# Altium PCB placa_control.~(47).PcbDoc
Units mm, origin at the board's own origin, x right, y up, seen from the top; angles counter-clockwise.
Board outline 58.75 x 106.25 mm, 2 copper layers (Top Layer, Bottom Layer); 36 components, 32 nets, 144 pads, 100 vias.
Unrouted connection lines stored in the file: 34.
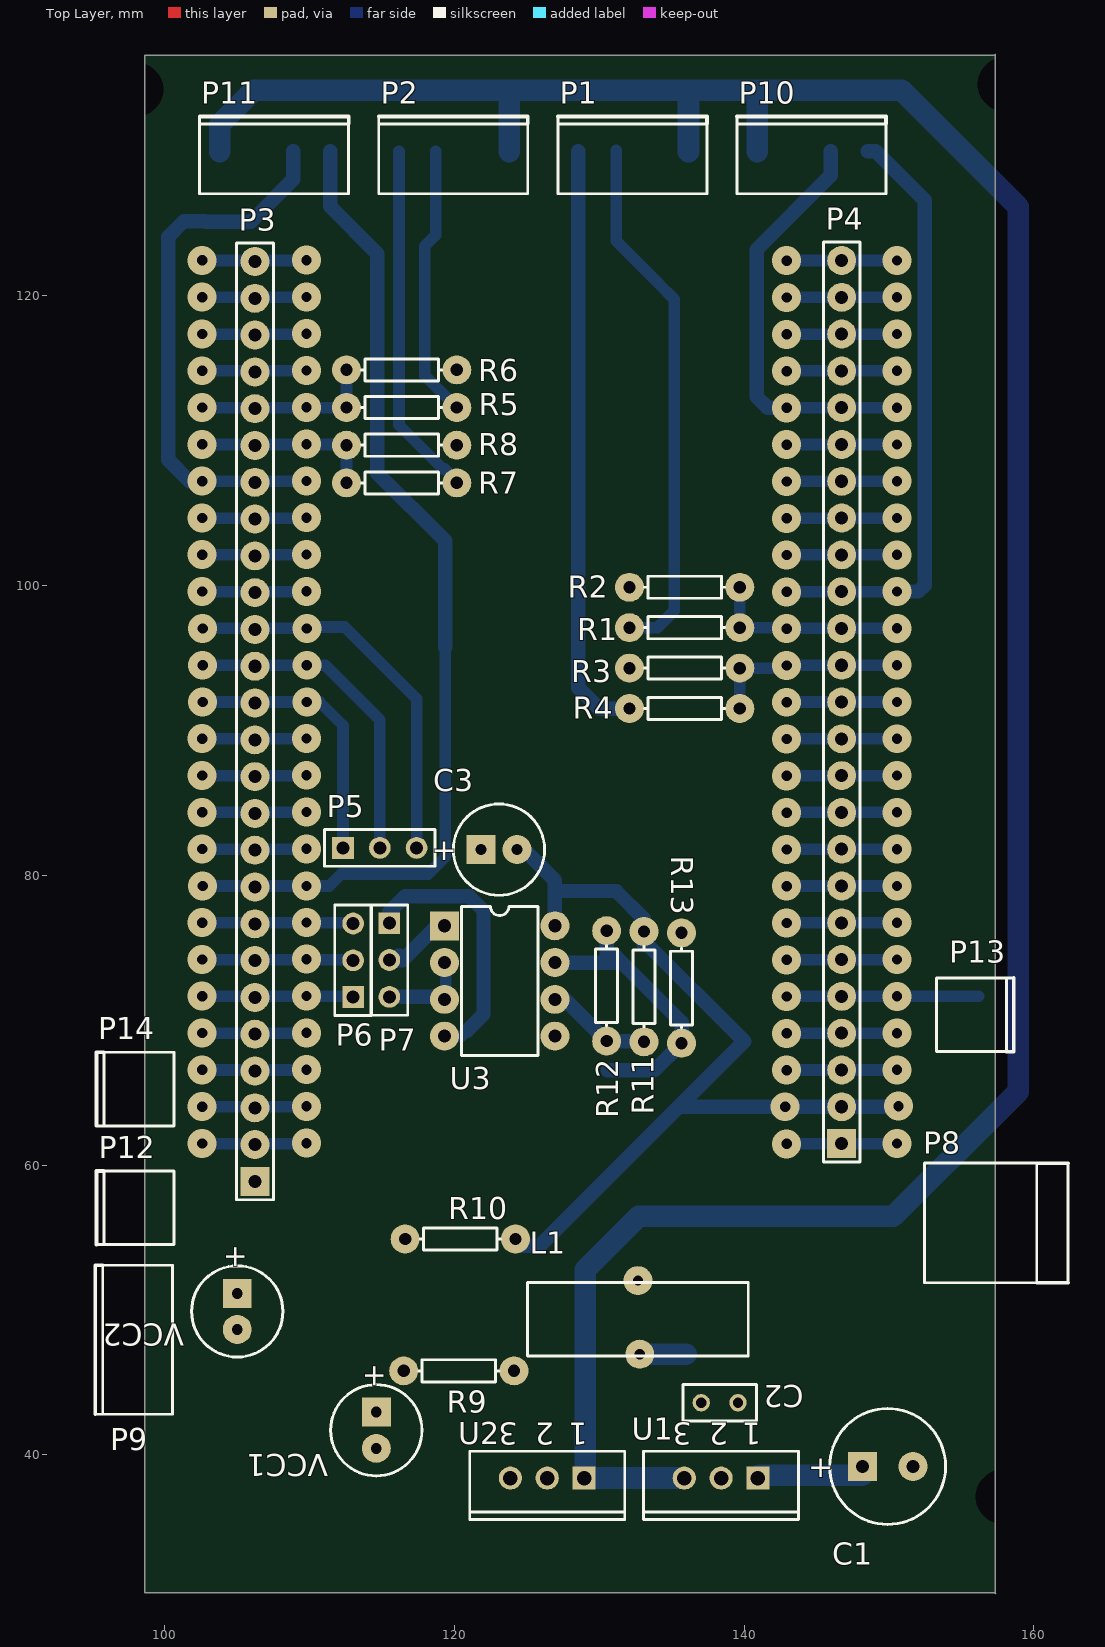
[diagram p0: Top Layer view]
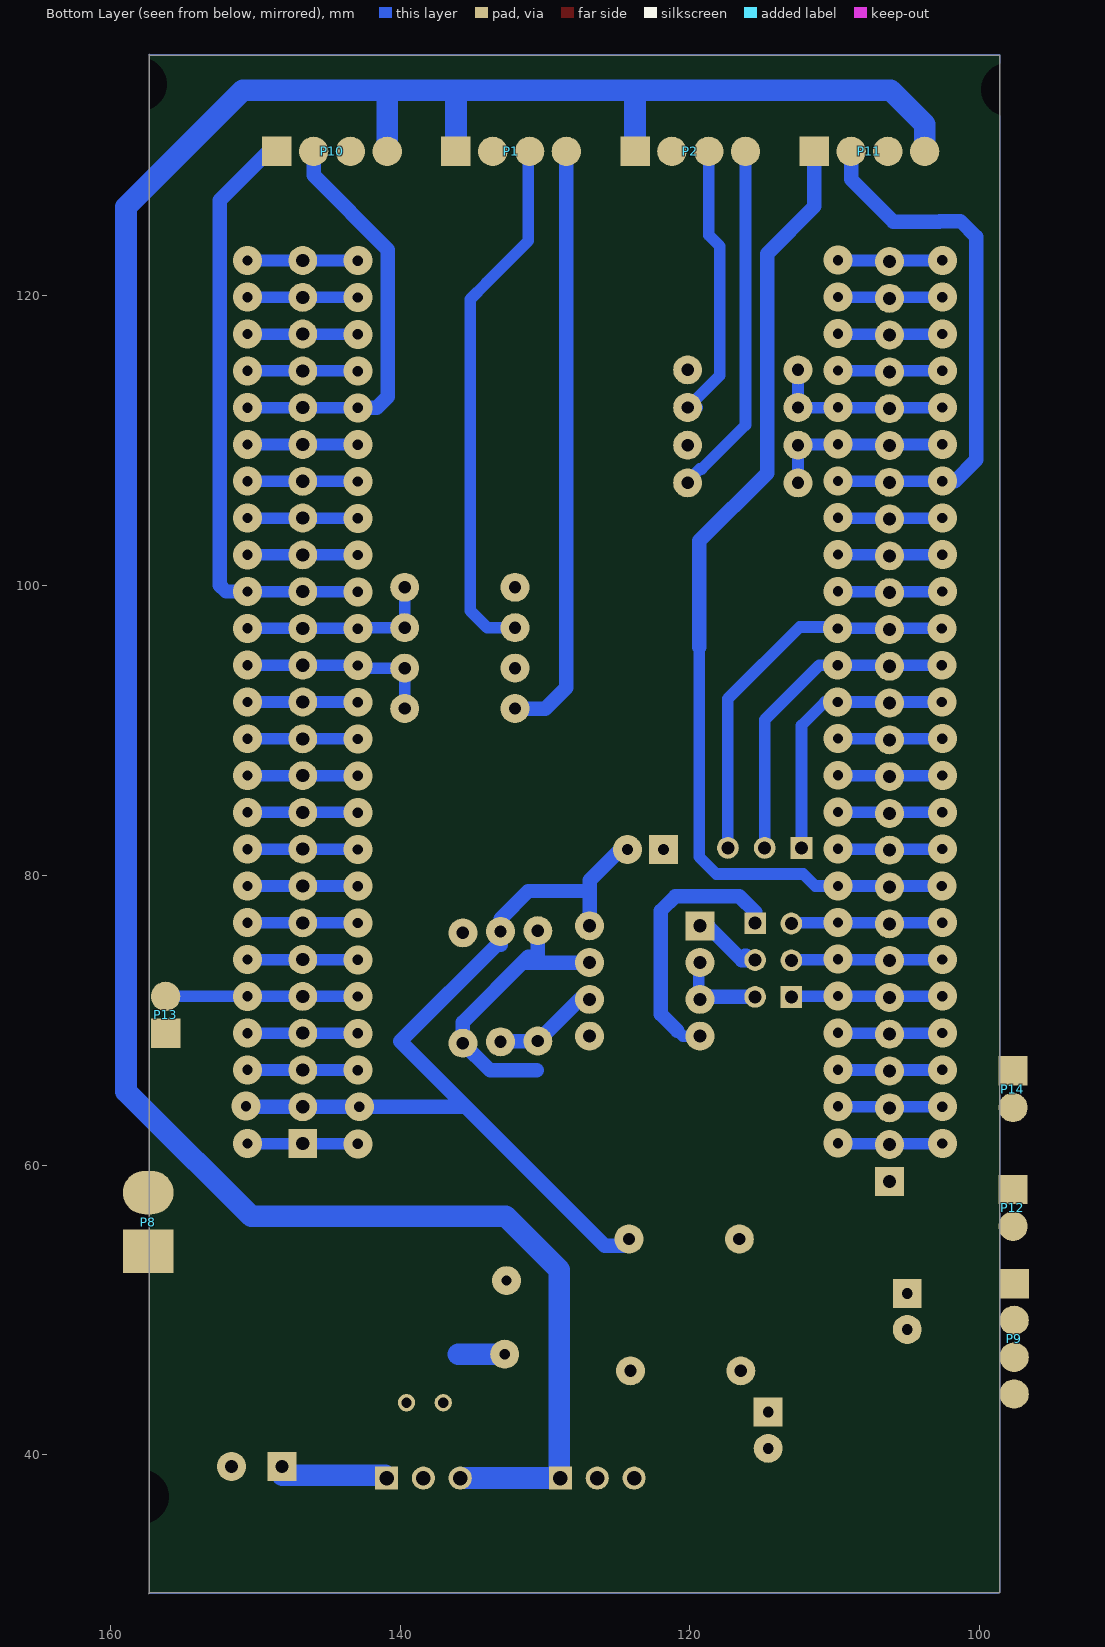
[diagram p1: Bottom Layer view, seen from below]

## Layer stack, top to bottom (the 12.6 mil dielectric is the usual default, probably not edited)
Top Layer: signal copper 0.0356
Dielectric: dielectric 0.32, FR-4, Dk 4.8
Bottom Layer: signal copper 0.0356

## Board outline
98.6,136.625 157.275,136.625 157.325,136.675 157.325,30.45 157.35,30.425 157.3,30.475 98.625,30.475 98.6,30.5

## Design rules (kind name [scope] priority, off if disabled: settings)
Clearance [All] p1: gap=0.4
ComponentClearance [All] p1: gap=0.254 collisioncheckmode=2 verticalgap=0.254
PlaneConnect [All] p1: planeconnectstyle=Direct reliefexpansion=0.508 reliefentries=4 reliefconductorwidth=0.6 reliefairgap=0.254
PolygonConnect [All] p1: connectstyle=Direct reliefconductorwidth=0.6 reliefentries=4 polygonreliefangle="90 Angle"
RoomDefinition REGULADOR [InComponentClass('REGULADOR')] p1: confinementstyle=ConfineIn formatcopy=TRUE lockcomponents=FALSE outline 99.475,34.9 155.025,34.9 155.025,58.375 99.475,58.375
RoomDefinition INTERFAZ [InComponentClass('INTERFAZ')] p2: confinementstyle=ConfineIn formatcopy=TRUE lockcomponents=FALSE outline 110.775,62.675 143.675,62.675 143.675,88.075 110.775,88.075
RoomDefinition ENCODER [InComponentClass('ENCODER')] p3: confinementstyle=ConfineOut formatcopy=TRUE lockcomponents=FALSE outline 141.4,147.25 141.4,152.45 116,152.45 116,147.25
RoomDefinition BOARD-ARM [InComponentClass('BOARD-ARM')] p4: confinementstyle=ConfineOut formatcopy=TRUE lockcomponents=FALSE outline 166.025,120.7 232.827,120.7 232.827,146.1 166.025,146.1
RoomDefinition placa_control_esquema [InComponentClass('placa_control_esquema')] p5: confinementstyle=ConfineIn formatcopy=TRUE lockcomponents=FALSE outline 93.3,34.925 163.875,34.925 163.875,136.6 93.3,136.6
RoutingVias [All] p1: holewidth=0.711 width=2 viastyle="Through Hole" minholewidth=0.711 minwidth=1.27 maxholewidth=0.711 maxwidth=2
SolderMaskExpansion [All] p1: expansion=0.102
TestPointUsage [All] p1: valid=0 allowmultiple=FALSE
Testpoint [All] p1: side=15 testpointundercomponent=TRUE minsize=1.016 maxsize=2.54 preferedsize=1.524 minholesize=0 maxholesize=1.016 preferedholesize=0.813 testpointgrid=0.025 style=1023 order=0-112345678
Width [All] p1: maxlimit=1.5 minlimit=0.8 preferedwidth=0.8
17 further rules are at their usual default settings.

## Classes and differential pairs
component class INTERFAZ: C3 P12 R11 R12 R13 U3
component class ENCODER: P1 P2 R1 R2 R3 R4 R5 R6 R7 R8
component class BOARD-ARM: P3 P4 P5 P6 P7 P13 P14
component class REGULADOR: C1 C2 L1 P8 R9 R10 U1 U2 VCC1 VCC2
component class placa_control_esquema: P9 P10 P11

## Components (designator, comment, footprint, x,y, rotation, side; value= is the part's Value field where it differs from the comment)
C1 "Cap Pol3" CAPPR3.5-8X15 149.9,39.2 r0 top
C2 "Cap" RAD-0.1 138.3,43.6 r0 top
C3 "Cap" CAPPR2.5-6.3X5 123.069,81.783 r0 top
L1 "Inductor Iron" bobina_Choque 135.2,51.9 r180 top
P1 "Header 4" HDR1X5 128.533,137.6 r180 top
P2 "Header 4" HDR1X5 116.167,137.6 r180 top
P3 "header26" HDR1x26 111.3,91.9 r90 top
P4 "Header 25" HDR1X25 146.73,61.49 r90 top
P5 "Header 3" HDR1X3 112.3,81.9 r0 top
P6 "Header 3" HDR1X3 113,71.6 r90 top
P7 "Header 3" HDR1X3 115.5,76.7 r270 top
P8 "Header 2" pwheader1x2 157.4,56.2 r90 top
P9 "Header 4" HDR1X5 90,44.2 r270 top
P10 "Header 4" HDR1X5 140.9,137.6 r180 top
P11 "Header 4" HDR1X5 103.8,137.6 r180 top
P12 "Header 2" wf2s 97.7,50.7 r270 top
P13 "Header 2" wf2s 156.2,76.725 r90 top
P14 "Header 2" wf2s 97.7,58.9 r270 top
R1 "metal film 2%" AXIAL-0.3 135.884,97.102 r180 top
R2 "metal film 2%" AXIAL-0.3 135.884,99.894 r0 top
R3 "metal film 2%" AXIAL-0.3 135.884,91.518 r180 top
R4 "metal film 2%" AXIAL-0.3 135.884,94.31 r0 top
R5 "metal film 2%" AXIAL-0.3 116.35,112.3 r0 top
R6 "metal film 2%" AXIAL-0.3 116.35,114.9 r180 top
R7 "metal film 2%" AXIAL-0.3 116.35,107.1 r0 top
R8 "metal film 2%" AXIAL-0.3 116.35,109.7 r180 top
R9 "Carbon 1/8w 5%" AXIAL-0.3 120.3,45.8 r0 top
R10 "Carbon 1/8w 5%" AXIAL-0.3 120.4,54.9 r0 top
R11 "Carbon 1/8w 5%" AXIAL-0.3 133.075,72.325 r90 top
R12 "Carbon 1/8w 5%" AXIAL-0.3 130.501,72.375 r270 top
R13 "Carbon 1/8w 5%" AXIAL-0.3 135.675,72.225 r270 top
U1 "LM78L12ACZ" T03B 138.4,38.4 r180 top
U2 "LM78L05ACZ" T03B 126.4,38.4 r180 top
U3 "SN75176BP" 626-05 123.119,72.715 r270 top
VCC1 "LED2" CAPPR2.5-6.3X5 114.6,41.7 r270 top
VCC2 "LED2" CAPPR2.5-6.3X5 105,49.9 r270 top

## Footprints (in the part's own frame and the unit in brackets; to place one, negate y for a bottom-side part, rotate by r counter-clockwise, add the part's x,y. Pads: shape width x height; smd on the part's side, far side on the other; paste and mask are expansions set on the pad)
626-05 [mm] "DIP; 8 Leads; Row Spacing 7.62 mm; Pitch 2.54 mm"
  rect 2x2 hole 0.9: 1(-3.81,-3.81)
  round 2 hole 0.9: 2(-1.27,-3.81) 3(1.27,-3.81) 4(3.81,-3.81) 5(3.81,3.81) 6(1.27,3.81) 7(-1.27,3.81) 8(-3.81,3.81)
  silkscreen extent -5.15,-2.65 5.15,2.65
AXIAL-0.3 [mm] "Resistor; 2 Leads"
  round 2 hole 0.85: 1(-3.81,0) 2(3.81,0)
  silkscreen extent -2.77,-0.76 2.77,0.76
bobina_Choque [mm]
  round 2 hole 0.7: 1(2.54,-0.127) 2(2.413,4.953)
  silkscreen extent -5.08,0 10.16,5.08
CAPPR2.5-6.3X5 [mm] "Capacitor, Electrolytic, Radial; Body 6.3 x 5 mm (Dia.xH typ); Pin Spacing 2.5 mm (typ)"
  rect 2x2 hole 0.75: 1(-1.25,0)
  round 2 hole 0.75: 2(1.25,0)
  silkscreen extent -3.15,-3.15 3.15,3.15
CAPPR3.5-8X15 [mm] "Capacitor, Electrolytic, Radial; Body 8 x 15 mm (Dia.xH typ); Pin Spacing 3.5 mm (typ)"
  rect 2x2 hole 0.9: 1(-1.75,0)
  round 2 hole 0.9: 2(1.75,0)
  silkscreen extent -4,-4 4,4
HDR1X3 [mm] "Connector; Header; 3 Position"
  rect 1.5x1.5 hole 0.9: 1(0,0)
  round 1.5 hole 0.9: 2(2.54,0) 3(5.08,0)
  silkscreen extent -1.27,-1.27 6.35,1.27
HDR1X5 [mil]
  rect 80x80 smd far side: 1(-300,300)
  round 80 smd far side: 2(-200,300) 3(-100,300) 4(0,300)
  silkscreen extent -350,205 55,415
HDR1X25 [mm] "Connector; Header; 25 Position"
  rect 2x2 hole 0.9: 1(0,0)
  round 2 hole 0.9: 2(2.54,0) 3(5.08,0) 4(7.62,0) 5(10.16,0) 6(12.7,0) 7(15.24,0) 8(17.78,0) 9(20.32,0) 10(22.86,0) 11(25.4,0) 12(27.94,0) 13(30.48,0) 14(33.02,0) 15(35.56,0) 16(38.1,0) 17(40.64,0) 18(43.18,0) 19(45.72,0) 20(48.26,0) 21(50.8,0) 22(53.34,0) 23(55.88,0) 24(58.42,0) 25(60.96,0)
  silkscreen extent -1.27,-1.27 62.23,1.27
HDR1x26 [mm]
  rect 2x2 hole 0.9: 1(-33.02,5.08)
  round 2 hole 0.9: 2(-30.48,5.08) 3(-27.94,5.08) 4(-25.4,5.08) 5(-22.86,5.08) 6(-20.32,5.08) 7(-17.78,5.08) 8(-15.24,5.08) 9(-12.7,5.08) 10(-10.16,5.08) 11(-7.62,5.08) 12(-5.08,5.08) 13(-2.54,5.08) 14(0,5.08) 15(2.54,5.08) 16(5.08,5.08) 17(7.62,5.08) 18(10.16,5.08) 19(12.7,5.08) 20(15.24,5.08) 21(17.78,5.08) 22(20.32,5.08) 23(22.86,5.08) 24(25.4,5.08) 25(27.94,5.08) 26(30.48,5.08)
  silkscreen extent -34.29,3.81 31.75,6.35
pwheader1x2 [mm]
  rect 3x3.5 smd far side: 1(-2.159,0)
  oval 3x3.5 smd far side: 2(1.905,0)
  silkscreen extent -4.32,-4.95 3.94,4.95
RAD-0.1 [mm] "Indicating Instrument; 2 Leads"
  round 1.2 hole 0.7: 1(-1.27,0) 2(1.27,0)
  silkscreen extent -2.54,-1.27 2.54,1.27
T03B [mm] "TO, Thru-Hole, Vertical, Heatsink Mounted; 3 In-Line Leads; Pitch 2.54 mm"
  rect 1.6x1.6 hole 1: 1(-2.54,0)
  round 1.6 hole 1: 2(0,0) 3(2.54,0)
  silkscreen extent -5.35,-1.85 5.35,2.85
wf2s [mil]
  rect 80x80 smd far side: 1(-300,0)
  round 80 smd far side: 2(-200,0)
  silkscreen extent -350,-95 -150,115

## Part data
C1: "Polarized Capacitor 35V"
C2 C3: "Capacitor"
L1: "Magnetic-Core Inductor"
P1 P2 P9 P10 P11: "Header, 4-Pin"
P3: library part Component_1
P4: "Header, 25-Pin"
P5 P6 P7: "Header, 3-Pin"
P8 P12 P13 P14: "Header, 2-Pin"
R1 R2 R3 R4 R5 R6 R7 R8 R9 R10 R11 R12 R13: library part "Res Semi", "Semiconductor Resistor"
U1 U2: "3-Terminal Positive Regulator"
U3: "Differential Bus Transceiver"
VCC1 VCC2: "Typical RED, GREEN, YELLOW, AMBER GaAs LED"

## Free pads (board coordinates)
  round 1.524 hole 3.75: 0(95.775,37.35) 0(98.025,134.25) 0(157.85,37.1) 0(157.975,134.625)

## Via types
v1: diameter 2, hole 0.711, Top Layer to Bottom Layer, 100 vias

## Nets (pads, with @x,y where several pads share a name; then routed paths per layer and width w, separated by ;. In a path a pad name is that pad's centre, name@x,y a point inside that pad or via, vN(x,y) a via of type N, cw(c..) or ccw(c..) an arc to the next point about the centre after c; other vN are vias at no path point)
+5V: C3.2 P4.2 P9.2 R10.2 R11.2 U2.3 U3.8 | length 59.8
  Bottom Layer w1: R10.2@124.325,54.425 125.875,54.425 140,68.55 133.075,75.475 R11.2@133.075,75.225 ; C3.2@124.817,81.783 126.929,79.671 U3.8 U3.8@127.15,76.525 ; 126.929,78.925 131.15,78.925 R11.2@133.075,77 ; 135.547,64.03 v1@150.505,64.03
  other v1: 142.825,64.03 150.65,64.075
+12V: P1.1 P2.1 P9.4 P10.4 P11.4 R9.2 U1.3 U2.1 | length 191.4
  Bottom Layer w1.5: P11.4 103.8,131.85 106.15,134.2 150.875,134.2 158.925,126.15 158.925,65.075 154.125,60.275 154.075,60.275 150.275,56.475 132.725,56.475 129.025,52.775 129.025,38.4 U1.3@135.9,38.4 ; P2.1 123.787,134.112 123.875,134.2 ; P1.1 136.153,134.053 136.3,134.2 ; 140.8,134.2 140.9,134.1 P10.4
D/~E: P7.3 U3.2 U3.3 | length 6.7
  Bottom Layer w0.8: U3.3 119.385,71.52 119.385,74.015 U3.2@119.425,73.975
  Bottom Layer w1: P7.3 119.134,71.62 U3.3 ; U3.3@119.29,71.92 U3.3@119.385,71.825
D/~E_0: P3.14 P5.1 | length 18.8
  Bottom Layer w0.8: v1(102.615,91.97) 110.68,91.97 112.3,90.35 P5.1
  other v1: 109.8,91.97
D/~E_1: P3.6 P6.1 | length 10.4
  Bottom Layer w0.8: v1@102.615,71.65 112.95,71.65 P6.1
  other v1: 102.575,71.66 109.775,71.675
DRIVER: P7.1 U3.4 | length 18.6
  Bottom Layer w0.8: U3.4 120.48,68.905 120.862,69.287
  Bottom Layer w1: P7.1 115.5,77.475 116.6,78.575 121,78.575 122,77.575 122,70.425 120.862,69.287
GND: C1.2 C2.1 C3.1 P1.2 P2.2 P4.1 P8.1 P9.1 P9.3 P10.3 P11.3 P13.1 P14.1 R2.1 R4.1 R6.1 R8.1 R13.1 U1.2 U2.2 U3.5 VCC1.2 VCC2.2 | length 7.2
  Bottom Layer w0.8: v1@143.23,61.49 v1@150.415,61.49
  other v1: 142.925,61.475 150.55,61.495
IN_B_L: P3.2 P14.2 | length 7.2
  Bottom Layer w0.8: v1@102.615,61.49 v1@109.8,61.49
  other v1: 102.575,61.5 109.775,61.515
IN_SD_1: P4.21 P10.2 | length 28.6
  Bottom Layer w0.8: v1@143.23,112.29 v1@150.415,112.29
  Bottom Layer w1: v1(142.925,112.275) 141.625,112.275 140.85,113.05 140.85,123.2 145.98,128.33 P10.2
  other v1: 150.55,112.295
IN_SD_2: P3.20 P11.2 | length 37.8
  Bottom Layer w0.8: v1@102.615,107.21 v1@109.8,107.21
  Bottom Layer w1: v1(102.575,107.22) 101.705,107.22 100.225,108.7 100.225,124.075 101.325,125.175 102.75,125.175 102.8,125.125 105.95,125.125 108.88,128.055 P11.2
  other v1: 109.775,107.235
NetC1_1: C1.1 C2.2 L1.2 U1.1 | length 10.4
  Bottom Layer w1.5: L1.2 135.978,46.947 ; U1.1@140.94,38.5 141.04,38.6 C1.1@148.15,38.6
NetL1_1: L1.1 P8.2
NetP1_3: P1.3 R1.2 | length 37
  Bottom Layer w0.8: P1.3@131.175,130.05 131.175,123.8 134.05,120.925 134.05,120.9 135.175,119.775 135.175,98.275 134.002,97.102 R1.2
NetP1_4: P1.4 R3.2 | length 41.2
  Bottom Layer w1: P1.4 128.533,92.967 129.982,91.518 R3.2
NetP2_3: P2.3 R5.2 | length 19.6
  Bottom Layer w0.8: P2.3 118.707,124.207 117.948,123.448 117.948,114.512 R5.2 R5.2@119.5,112.3
NetP2_4: P2.4 R7.2 | length 24.7
  Bottom Layer w0.8: P2.4 116.167,111.093 119.204,108.056 119.319,108.056 R7.2@120.325,107.05
NetP3_21: P3.21 R7.1 R8.2 | length 12.5
  Bottom Layer w0.8: v1@102.615,109.75 112.49,109.75 R8.2 R7.1
  other v1: 102.575,109.76 109.775,109.775
NetP3_22: P3.22 R5.1 R6.2 | length 12.6
  Bottom Layer w0.8: v1@102.615,112.29 112.53,112.29 R5.1@112.5,112.32 ; R5.1 R6.2
  other v1: 102.575,112.3 109.775,112.315
NetP4_14: P4.14 R3.1 R4.2 | length 13
  Bottom Layer w0.8: R3.1 R4.2 v1@142.74,94.31 ; v1@143.23,94.51 v1@150.415,94.51
  other v1: 142.925,94.495 150.55,94.515
NetP4_15: P4.15 R1.1 R2.2 | length 13.1
  Bottom Layer w0.8: R2.2 R1.1 v1@142.858,97.102 ; v1@143.23,97.05 v1@150.415,97.05
  other v1: 142.925,97.035 150.55,97.055
NetP12_1: P12.1 R11.1 R12.2 U3.6 | length 8
  Bottom Layer w1: U3.6 127.621,71.445 R12.2 ; R12.2@130.125,68.825 R12.2@130.375,68.825 ; R12.2@130.501,68.951 R12.2 ; R11.1 133.025,68.565 R12.2
NetP12_2: P12.2 R12.1 R13.2 U3.7 | length 20.8
  Bottom Layer w1: U3.7 131.54,73.985 ; R12.1@130.541,76.225 R12.1 130.501,74.374 131.151,74.374 135.675,69.85 135.675,68.425 133.785,66.535 130.56,66.535
NetR9_1: R9.1 VCC1.1
NetR10_1: R10.1 VCC2.1
PWM_1: P4.16 P10.1 | length 41.1
  Bottom Layer w0.8: v1@143.23,99.59 v1@150.415,99.59
  Bottom Layer w1: P10.1 149.07,129.98 152.45,126.6 152.45,100.025 152.025,99.6 v1@150.65,99.6
  other v1: 142.925,99.575 150.55,99.595
PWM_2: P3.9 P11.1 | length 76.9
  Bottom Layer w0.8: v1(102.615,79.27) 111.345,79.27 112.175,80.1 118.175,80.1 119.35,81.275 119.35,103.1
  Bottom Layer w1: P11.1 111.42,126.18 114.675,122.925 114.675,107.775 119.35,103.1 119.35,95.75
  other v1: 109.775,79.27
RECIEVER: P7.2 U3.1 | length 5.1
  Bottom Layer w1: P7.2 116.435,74.16 U3.1@118.825,76.55 ; P7.2@116.1,74.45 116.2,74.45 ; U3.1@118.725,76.55 U3.1@119.45,76.55
RESET: P4.5 P13.2 | length 12.8
  Bottom Layer w0.8: v1@143.23,71.65 v1@150.415,71.65 ; v1(150.55,71.655) 156.19,71.655 P13.2
  other v1: 142.925,71.635
RX_0: P3.15 P5.2 | length 22.6
  Bottom Layer w0.8: v1(102.615,94.51) 111.065,94.51 114.84,90.735 P5.2
  other v1: 109.8,94.51
RX_1: P3.7 P6.2 | length 10.4
  Bottom Layer w0.8: v1@102.615,74.19 112.95,74.19 P6.2
  other v1: 102.575,74.2 109.775,74.215
TX_0: P3.16 P5.3 | length 27.1
  Bottom Layer w0.8: v1(102.615,97.05) v1(109.8,97.05) ; v1@109.825,97.15 112.425,97.15 117.38,92.195 P5.3
TX_1: P3.8 P6.3 | length 10.4
  Bottom Layer w0.8: v1@102.615,76.73 112.95,76.73 P6.3
  other v1: 102.575,76.74 109.775,76.755
pads on no net: P3.1 P3.3 P3.4 P3.5 P3.10 P3.11 P3.12 P3.13 P3.17 P3.18 P3.19 P3.23 P3.24 P3.25 P3.26 P4.3 P4.4 P4.6 P4.7 P4.8 P4.9 P4.10 P4.11 P4.12 P4.13 P4.17 P4.18 P4.19 P4.20 P4.22 P4.23 P4.24 P4.25
copper on no net: | length 229.9
  Bottom Layer w0.8: v1@102.615,64.03 v1@109.8,64.03 ; v1@102.615,66.57 v1@109.8,66.57 ; v1@102.615,69.11 v1@109.8,69.11 ; v1@102.615,81.81 v1@109.775,81.81 ; v1@102.615,84.35 v1@109.8,84.35 ; v1@102.615,86.89 v1@109.8,86.89 ; v1@102.615,89.43 v1@109.8,89.43 ; v1@102.615,99.59 v1@109.8,99.59 ; v1@102.615,102.13 v1@109.8,102.13 ; v1@102.615,104.67 v1@109.8,104.67 ; v1@102.615,114.83 v1@109.8,114.83 ; v1@102.615,117.37 v1@109.8,117.37 ; v1@102.615,119.91 v1@109.8,119.91 ; v1@102.615,122.45 v1@109.8,122.45 ; v1@143.23,66.57 v1@150.415,66.57 ; v1@143.23,69.11 v1@150.415,69.11 ; v1@143.23,74.19 v1@150.415,74.19 ; v1@143.23,76.73 v1@150.415,76.73 ; v1@143.23,79.27 v1@150.415,79.27 ; v1@143.23,81.81 v1@150.415,81.81 ; v1@143.23,84.35 v1@150.415,84.35 ; v1@143.23,86.89 v1@150.415,86.89 ; v1@143.23,89.43 v1@150.415,89.43 ; v1@143.23,91.97 v1@150.415,91.97 ; v1@143.23,102.13 v1@150.415,102.13 ; v1@143.23,104.67 v1@150.415,104.67 ; v1@143.23,107.21 v1@150.415,107.21 ; v1@143.23,109.75 v1@150.415,109.75 ; v1@143.23,114.83 v1@150.415,114.83 ; v1@143.23,117.37 v1@150.415,117.37 ; v1@143.23,119.91 v1@150.415,119.91 ; v1@143.23,122.45 v1@150.415,122.45
  other v1: 102.575,64.04 109.775,64.055 142.925,66.555 102.575,66.58 150.55,66.575 109.775,66.595 142.925,69.095 102.575,69.12 150.55,69.115 109.775,69.135 142.925,74.175 150.55,74.195 142.925,76.715 150.55,76.735 142.925,79.255 150.55,79.275 142.925,81.795 102.575,81.82 150.55,81.815 109.775,81.835 142.925,84.335 102.575,84.36 150.55,84.355 109.775,84.375 142.925,86.875 102.575,86.9 150.55,86.895 109.775,86.915 142.925,89.415 102.575,89.44 150.55,89.435 109.775,89.455 142.925,91.955 150.55,91.975 102.575,99.6 109.775,99.615 142.925,102.115 102.575,102.14 150.55,102.135 109.775,102.155 142.925,104.655 102.575,104.68 150.55,104.675 109.775,104.695 142.925,107.195 150.55,107.215 142.925,109.735 150.55,109.755 142.925,114.815 102.575,114.84 150.55,114.835 109.775,114.855 142.925,117.355 102.575,117.38 150.55,117.375 109.775,117.395 142.925,119.895 102.575,119.92 150.55,119.915 109.775,119.935 142.925,122.435 102.575,122.46 150.55,122.455 109.775,122.475

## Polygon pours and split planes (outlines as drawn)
GND on Bottom Layer "plano_señal_fuerte" (solid, remove dead copper, shelved, pour order 1000): 98.575,136.606 98.627,136.65 157.35,136.65 157.324,136.628 157.324,30.472 157.35,30.45 98.704,30.45 98.627,30.517 98.575,30.561

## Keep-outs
Drill Guide:
  rectangle: 103.975,54.175 149.375,124.375

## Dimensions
163.425,142.45 to 93.325,142.575 on Top Layer
169.675,136.65 to 167.925,35.675 on Bottom Layer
